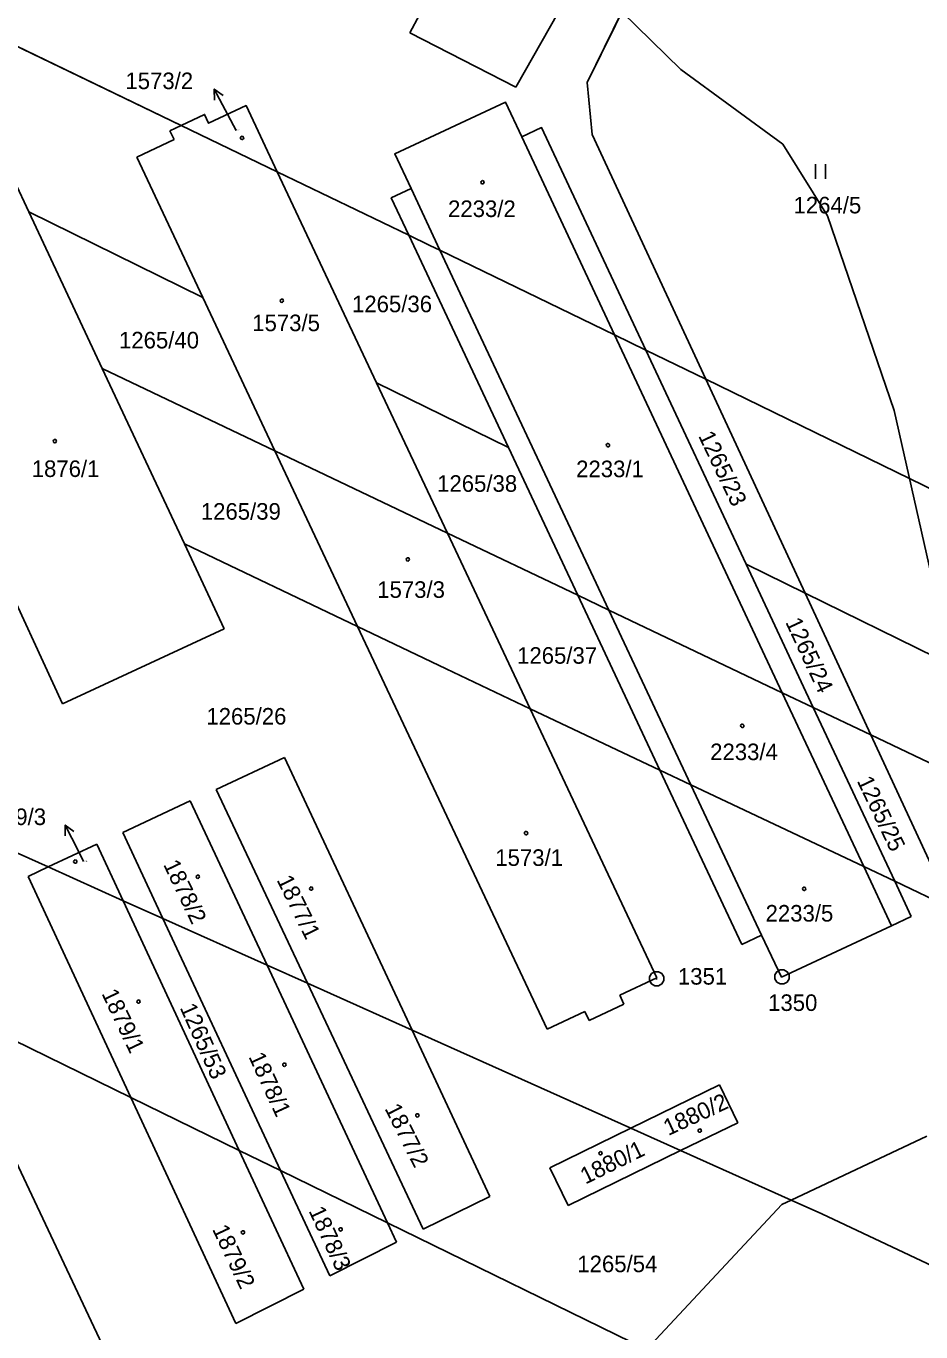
# Model space of a CAD drawing. Extents: x -779618 to -776429, y -1144546 to -1143350.
# Drawn here: x -777167.4 to -777075.6, y -1144114.1 to -1143980.2 of the extents above; entities that cross this region are included whole.
import ezdxf

# ---------------------------------------------------------------- set-up
doc = ezdxf.new("R2010")
doc.units = 0
for name, color, linetype in [('1', 7, 'Continuous'), ('11', 7, 'Continuous'), ('12', 7, 'Continuous'), ('2', 7, 'Continuous'), ('3', 7, 'Continuous'), ('4', 7, 'Continuous'), ('5', 7, 'Continuous'), ('7', 7, 'Continuous'), ('8', 7, 'Continuous')]:
    doc.layers.add(name, color=color, linetype=linetype)

msp = doc.modelspace()

# ---------------------------------------------------------------- linework, layer by layer
at = {"layer": '1'}
for p, q in [((-777093.52, -1143952.82), (-777109.82, -1143985.95)), ((-777128.02, -1143980.84), (-777120.78, -1143967.25)), ((-777109.82, -1143973.51), (-777117.13, -1143986.44)), ((-777182.11, -1143975.59), (-777151.49, -1143990.35)), ((-777117.13, -1143986.44), (-777128.02, -1143980.84)), ((-777109.82, -1143985.95), (-777109.29, -1143991.28)), ((-777148.68, -1143990.13), (-777144.83, -1143988.32)), ((-777144.83, -1143988.32), (-777141.63, -1143995.11)), ((-777129.57, -1143993.28), (-777118.21, -1143987.96)), ((-777118.21, -1143987.96), (-777116.54, -1143991.53)), ((-777151.49, -1143990.35), (-777149.1, -1143989.23)), ((-777149.1, -1143989.23), (-777148.68, -1143990.13)), ((-777152.65, -1143990.9), (-777151.49, -1143990.35)), ((-777152.22, -1143991.8), (-777152.65, -1143990.9)), ((-777151.49, -1143990.35), (-777141.63, -1143995.11)), ((-777116.54, -1143991.53), (-777114.5, -1143990.57)), ((-777114.5, -1143990.57), (-777103.79, -1144013.4)), ((-777109.29, -1143991.28), (-777097.63, -1144016.39)), ((-777156.06, -1143993.61), (-777152.22, -1143991.8)), ((-777149.29, -1144007.99), (-777156.06, -1143993.61)), ((-777127.9, -1143996.84), (-777129.57, -1143993.28)), ((-777141.63, -1143995.11), (-777128.13, -1144001.62)), ((-777141.63, -1143995.11), (-777131.43, -1144016.75)), ((-777167.13, -1143999.23), (-777168.61, -1143996.07)), ((-777129.93, -1143997.79), (-777127.9, -1143996.84)), ((-777128.13, -1144001.62), (-777129.93, -1143997.79)), ((-777167.13, -1143999.23), (-777149.29, -1144007.99)), ((-777167.13, -1143999.23), (-777159.6, -1144015.3)), ((-777128.13, -1144001.62), (-777125.96, -1144002.66)), ((-777128.13, -1144001.62), (-777117.9, -1144023.39)), ((-777125.96, -1144002.66), (-777124.93, -1144003.16)), ((-777124.93, -1144003.16), (-777107.02, -1144011.84)), ((-777149.29, -1144007.99), (-777141.88, -1144023.74)), ((-777107.02, -1144011.84), (-777103.79, -1144013.4)), ((-777103.79, -1144013.4), (-777099.68, -1144015.4)), ((-777103.79, -1144013.4), (-777093.49, -1144035.37)), ((-777159.6, -1144015.3), (-777141.88, -1144023.74)), ((-777159.6, -1144015.3), (-777151.17, -1144033.27)), ((-777099.68, -1144015.4), (-777097.63, -1144016.39)), ((-777131.43, -1144016.75), (-777117.9, -1144023.39)), ((-777131.43, -1144016.75), (-777124.16, -1144032.18)), ((-777097.63, -1144016.39), (-777054.51, -1144037.4)), ((-777097.63, -1144016.39), (-777087.44, -1144038.34)), ((-777163.68, -1144049.68), (-777176.95, -1144020.96)), ((-777141.88, -1144023.74), (-777124.16, -1144032.18)), ((-777141.88, -1144023.74), (-777133.39, -1144041.77)), ((-777117.9, -1144023.39), (-777110.78, -1144038.56)), ((-777124.16, -1144032.18), (-777110.78, -1144038.56)), ((-777124.16, -1144032.18), (-777115.67, -1144050.19)), ((-777133.39, -1144041.77), (-777151.17, -1144033.27)), ((-777151.17, -1144033.27), (-777147.08, -1144042)), ((-777093.49, -1144035.37), (-777087.44, -1144038.34)), ((-777093.49, -1144035.37), (-777086.6, -1144050.07)), ((-777087.44, -1144038.34), (-777074.06, -1144044.91)), ((-777087.44, -1144038.34), (-777080.69, -1144052.88)), ((-777110.78, -1144038.56), (-777107.58, -1144040.08)), ((-777110.78, -1144038.56), (-777102.35, -1144056.49)), ((-777107.58, -1144040.08), (-777089.79, -1144048.55)), ((-777147.08, -1144042), (-777163.68, -1144049.68)), ((-777124.3, -1144046.11), (-777133.39, -1144041.77)), ((-777133.39, -1144041.77), (-777113.94, -1144083.08)), ((-777115.67, -1144050.19), (-777124.3, -1144046.11)), ((-777089.79, -1144048.55), (-777086.6, -1144050.07)), ((-777102.35, -1144056.49), (-777115.67, -1144050.19)), ((-777115.67, -1144050.19), (-777102.66, -1144077.8)), ((-777086.6, -1144050.07), (-777080.69, -1144052.88)), ((-777086.6, -1144050.07), (-777078.24, -1144067.9)), ((-777080.69, -1144052.88), (-777034.39, -1144074.95)), ((-777080.69, -1144052.88), (-777072.46, -1144070.64)), ((-777147.92, -1144058.49), (-777140.89, -1144055.19)), ((-777140.89, -1144055.19), (-777127.79, -1144083.17)), ((-777187.43, -1144056.45), (-777165.16, -1144066.43)), ((-777099.16, -1144058), (-777102.35, -1144056.49)), ((-777093.95, -1144074.37), (-777102.35, -1144056.49)), ((-777147.92, -1144058.49), (-777138.54, -1144078.35)), ((-777081.43, -1144066.39), (-777099.16, -1144058)), ((-777157.5, -1144062.89), (-777150.56, -1144059.63)), ((-777150.56, -1144059.63), (-777142.67, -1144076.5)), ((-777153.38, -1144071.71), (-777157.5, -1144062.89)), ((-777160.14, -1144064.08), (-777165.16, -1144066.43)), ((-777157.44, -1144069.89), (-777160.14, -1144064.08)), ((-777165.16, -1144066.43), (-777167.2, -1144067.39)), ((-777165.16, -1144066.43), (-777157.44, -1144069.89)), ((-777078.24, -1144067.9), (-777081.43, -1144066.39)), ((-777167.2, -1144067.39), (-777156.67, -1144090.07)), ((-777072.46, -1144070.64), (-777078.24, -1144067.9)), ((-777076.55, -1144071.5), (-777078.24, -1144067.9)), ((-777157.44, -1144069.89), (-777153.38, -1144071.71)), ((-777145.53, -1144095.5), (-777157.44, -1144069.89)), ((-777153.38, -1144071.71), (-777142.67, -1144076.5)), ((-777141.3, -1144097.57), (-777153.38, -1144071.71)), ((-777078.58, -1144072.46), (-777076.55, -1144071.5)), ((-777089.88, -1144077.75), (-777078.58, -1144072.46)), ((-777091.92, -1144073.41), (-777093.95, -1144074.37)), ((-777091.92, -1144073.41), (-777089.88, -1144077.75)), ((-777142.67, -1144076.5), (-777138.54, -1144078.35)), ((-777142.67, -1144076.5), (-777130.33, -1144102.93)), ((-777138.54, -1144078.35), (-777127.79, -1144083.17)), ((-777126.64, -1144103.57), (-777138.54, -1144078.35)), ((-777106.48, -1144079.59), (-777102.66, -1144077.8)), ((-777106.48, -1144079.59), (-777106.05, -1144080.5)), ((-777176.03, -1144080.61), (-777156.67, -1144090.07)), ((-777158.22, -1144118.36), (-777176.03, -1144080.61)), ((-777113.94, -1144083.08), (-777110.04, -1144081.26)), ((-777110.04, -1144081.26), (-777109.62, -1144082.17)), ((-777109.62, -1144082.17), (-777106.05, -1144080.5)), ((-777127.79, -1144083.17), (-777105.34, -1144093.23)), ((-777127.79, -1144083.17), (-777119.81, -1144100.22)), ((-777105.34, -1144093.23), (-777096.24, -1144088.79)), ((-777096.24, -1144088.79), (-777094.36, -1144092.67)), ((-777156.67, -1144090.07), (-777145.53, -1144095.5)), ((-777156.67, -1144090.07), (-777145.89, -1144113.28)), ((-777113.65, -1144097.29), (-777105.34, -1144093.23)), ((-777105.34, -1144093.23), (-777100.22, -1144095.52)), ((-777094.36, -1144092.67), (-777100.22, -1144095.52)), ((-777088.89, -1144100.6), (-777074.93, -1144094.03)), ((-777145.53, -1144095.5), (-777141.3, -1144097.57)), ((-777138.92, -1144109.73), (-777145.53, -1144095.5)), ((-777100.22, -1144095.52), (-777111.78, -1144101.16)), ((-777100.22, -1144095.52), (-777088.89, -1144100.6)), ((-777111.78, -1144101.16), (-777113.65, -1144097.29)), ((-777141.3, -1144097.57), (-777130.33, -1144102.93)), ((-777136.25, -1144108.38), (-777141.3, -1144097.57)), ((-777119.81, -1144100.22), (-777126.64, -1144103.57)), ((-777103.71, -1144115.92), (-777089.82, -1144101.04)), ((-777089.82, -1144101.04), (-777088.89, -1144100.6)), ((-777088.89, -1144100.6), (-777085.72, -1144102.02)), ((-776999, -1144142.97), (-777085.72, -1144102.02)), ((-777130.33, -1144102.93), (-777103.71, -1144115.92)), ((-777130.33, -1144102.93), (-777129.39, -1144104.93)), ((-777129.39, -1144104.93), (-777136.25, -1144108.38)), ((-777145.89, -1144113.28), (-777138.92, -1144109.73))]:
    msp.add_line(p, q, dxfattribs=at)
at = {"layer": '11'}
for points in [[(-777233.61, -1143950.34), (-777182.11, -1143975.59), (-777151.49, -1143990.35), (-777149.1, -1143989.23), (-777148.68, -1143990.13), (-777144.83, -1143988.32), (-777141.63, -1143995.11), (-777128.13, -1144001.62), (-777129.93, -1143997.79), (-777127.9, -1143996.84), (-777129.57, -1143993.28), (-777118.21, -1143987.96), (-777116.54, -1143991.53), (-777114.5, -1143990.57), (-777103.79, -1144013.4), (-777099.68, -1144015.4), (-777097.63, -1144016.39), (-777109.29, -1143991.28), (-777109.82, -1143985.95), (-777106.25, -1143978.69)], [(-777106.25, -1143978.69), (-777100.19, -1143984.61), (-777089.74, -1143992.29), (-777085.15, -1143999.64), (-777078.29, -1144019.61), (-777070.38, -1144054.63), (-777064.39, -1144074.9), (-777053.6, -1144104.13), (-777023.35, -1144200.11), (-777006.25, -1144273.89), (-776995.59, -1144305.77), (-776985.2, -1144331.09), (-776979.71, -1144341.4), (-776962.8, -1144366.65), (-776938.27, -1144396.78)]]:
    msp.add_lwpolyline(points, dxfattribs=at)
at = {"layer": '12'}
for p, q in [((-777148.68, -1143990.13), (-777144.83, -1143988.32)), ((-777144.83, -1143988.32), (-777141.63, -1143995.11)), ((-777129.57, -1143993.28), (-777118.21, -1143987.96)), ((-777118.21, -1143987.96), (-777116.54, -1143991.53)), ((-777151.49, -1143990.35), (-777149.1, -1143989.23)), ((-777149.1, -1143989.23), (-777148.68, -1143990.13)), ((-777152.65, -1143990.9), (-777151.49, -1143990.35)), ((-777152.22, -1143991.8), (-777152.65, -1143990.9)), ((-777116.54, -1143991.53), (-777107.02, -1144011.84)), ((-777156.06, -1143993.61), (-777152.22, -1143991.8)), ((-777149.29, -1144007.99), (-777156.06, -1143993.61)), ((-777127.9, -1143996.84), (-777129.57, -1143993.28)), ((-777141.63, -1143995.11), (-777131.43, -1144016.75)), ((-777167.13, -1143999.23), (-777168.61, -1143996.07)), ((-777127.9, -1143996.84), (-777124.93, -1144003.16)), ((-777167.13, -1143999.23), (-777159.6, -1144015.3)), ((-777124.93, -1144003.16), (-777107.58, -1144040.08)), ((-777149.29, -1144007.99), (-777141.88, -1144023.74)), ((-777107.02, -1144011.84), (-777089.79, -1144048.55)), ((-777159.6, -1144015.3), (-777151.17, -1144033.27)), ((-777131.43, -1144016.75), (-777124.16, -1144032.18)), ((-777163.68, -1144049.68), (-777176.95, -1144020.96)), ((-777141.88, -1144023.74), (-777133.39, -1144041.77)), ((-777124.16, -1144032.18), (-777115.67, -1144050.19)), ((-777151.17, -1144033.27), (-777147.08, -1144042)), ((-777107.58, -1144040.08), (-777099.16, -1144058)), ((-777147.08, -1144042), (-777163.68, -1144049.68)), ((-777133.39, -1144041.77), (-777113.94, -1144083.08)), ((-777089.79, -1144048.55), (-777081.43, -1144066.39)), ((-777115.67, -1144050.19), (-777102.66, -1144077.8)), ((-777147.92, -1144058.49), (-777140.89, -1144055.19)), ((-777140.89, -1144055.19), (-777127.79, -1144083.17)), ((-777147.92, -1144058.49), (-777138.54, -1144078.35)), ((-777099.16, -1144058), (-777091.92, -1144073.41)), ((-777157.5, -1144062.89), (-777150.56, -1144059.63)), ((-777150.56, -1144059.63), (-777142.67, -1144076.5)), ((-777153.38, -1144071.71), (-777157.5, -1144062.89)), ((-777160.14, -1144064.08), (-777165.16, -1144066.43)), ((-777157.44, -1144069.89), (-777160.14, -1144064.08)), ((-777165.16, -1144066.43), (-777167.2, -1144067.39)), ((-777081.43, -1144066.39), (-777078.58, -1144072.46)), ((-777167.2, -1144067.39), (-777156.67, -1144090.07)), ((-777145.53, -1144095.5), (-777157.44, -1144069.89)), ((-777141.3, -1144097.57), (-777153.38, -1144071.71)), ((-777089.88, -1144077.75), (-777078.58, -1144072.46)), ((-777091.92, -1144073.41), (-777089.88, -1144077.75)), ((-777142.67, -1144076.5), (-777130.33, -1144102.93)), ((-777126.64, -1144103.57), (-777138.54, -1144078.35)), ((-777106.48, -1144079.59), (-777102.66, -1144077.8)), ((-777106.48, -1144079.59), (-777106.05, -1144080.5)), ((-777158.22, -1144118.36), (-777176.03, -1144080.61)), ((-777113.94, -1144083.08), (-777110.04, -1144081.26)), ((-777110.04, -1144081.26), (-777109.62, -1144082.17)), ((-777109.62, -1144082.17), (-777106.05, -1144080.5)), ((-777127.79, -1144083.17), (-777119.81, -1144100.22)), ((-777105.34, -1144093.23), (-777096.24, -1144088.79)), ((-777096.24, -1144088.79), (-777094.36, -1144092.67)), ((-777156.67, -1144090.07), (-777145.89, -1144113.28)), ((-777113.65, -1144097.29), (-777105.34, -1144093.23)), ((-777094.36, -1144092.67), (-777100.22, -1144095.52)), ((-777138.92, -1144109.73), (-777145.53, -1144095.5)), ((-777100.22, -1144095.52), (-777111.78, -1144101.16)), ((-777111.78, -1144101.16), (-777113.65, -1144097.29)), ((-777136.25, -1144108.38), (-777141.3, -1144097.57)), ((-777119.81, -1144100.22), (-777126.64, -1144103.57)), ((-777130.33, -1144102.93), (-777129.39, -1144104.93)), ((-777129.39, -1144104.93), (-777136.25, -1144108.38)), ((-777145.89, -1144113.28), (-777138.92, -1144109.73))]:
    msp.add_line(p, q, dxfattribs=at)
at = {"layer": '3'}
for p, q in [((-777086.36, -1143994.34), (-777086.36, -1143995.84)), ((-777085.36, -1143995.84), (-777085.36, -1143994.34))]:
    msp.add_line(p, q, dxfattribs=at)
at = {"layer": '4'}
for p, q in [((-777116.54, -1143991.53), (-777107.02, -1144011.84)), ((-777127.9, -1143996.84), (-777124.93, -1144003.16)), ((-777124.93, -1144003.16), (-777107.58, -1144040.08)), ((-777107.02, -1144011.84), (-777089.79, -1144048.55)), ((-777107.58, -1144040.08), (-777099.16, -1144058)), ((-777089.79, -1144048.55), (-777081.43, -1144066.39)), ((-777099.16, -1144058), (-777091.92, -1144073.41)), ((-777081.43, -1144066.39), (-777078.58, -1144072.46))]:
    msp.add_line(p, q, dxfattribs=at)
at = {"layer": '5'}
for points in [[(-777145.25, -1143991.47), (-777145.15, -1143991.49), (-777145.1, -1143991.58), (-777145.08, -1143991.64), (-777145.1, -1143991.73), (-777145.18, -1143991.8), (-777145.25, -1143991.81), (-777145.34, -1143991.78), (-777145.4, -1143991.72), (-777145.42, -1143991.64), (-777145.4, -1143991.55), (-777145.32, -1143991.48)], [(-777120.56, -1143996.02), (-777120.46, -1143996.04), (-777120.41, -1143996.13), (-777120.39, -1143996.19), (-777120.41, -1143996.28), (-777120.49, -1143996.35), (-777120.56, -1143996.36), (-777120.65, -1143996.33), (-777120.71, -1143996.27), (-777120.73, -1143996.19), (-777120.71, -1143996.1), (-777120.63, -1143996.03)], [(-777141.16, -1144008.17), (-777141.06, -1144008.19), (-777141.01, -1144008.28), (-777140.99, -1144008.34), (-777141.01, -1144008.43), (-777141.09, -1144008.5), (-777141.16, -1144008.51), (-777141.25, -1144008.48), (-777141.31, -1144008.42), (-777141.33, -1144008.34), (-777141.31, -1144008.25), (-777141.23, -1144008.18)], [(-777164.47, -1144022.57), (-777164.37, -1144022.59), (-777164.32, -1144022.68), (-777164.3, -1144022.74), (-777164.32, -1144022.83), (-777164.4, -1144022.9), (-777164.47, -1144022.91), (-777164.56, -1144022.88), (-777164.62, -1144022.82), (-777164.64, -1144022.74), (-777164.62, -1144022.65), (-777164.54, -1144022.58)], [(-777107.68, -1144022.99), (-777107.58, -1144023.01), (-777107.53, -1144023.1), (-777107.51, -1144023.16), (-777107.53, -1144023.25), (-777107.61, -1144023.32), (-777107.68, -1144023.33), (-777107.77, -1144023.3), (-777107.83, -1144023.24), (-777107.85, -1144023.16), (-777107.83, -1144023.07), (-777107.75, -1144023)], [(-777128.23, -1144034.7), (-777128.13, -1144034.72), (-777128.08, -1144034.81), (-777128.06, -1144034.87), (-777128.08, -1144034.96), (-777128.16, -1144035.03), (-777128.23, -1144035.04), (-777128.32, -1144035.01), (-777128.38, -1144034.95), (-777128.4, -1144034.87), (-777128.38, -1144034.78), (-777128.3, -1144034.71)], [(-777093.89, -1144051.78), (-777093.79, -1144051.8), (-777093.74, -1144051.89), (-777093.72, -1144051.95), (-777093.74, -1144052.04), (-777093.82, -1144052.11), (-777093.89, -1144052.12), (-777093.98, -1144052.09), (-777094.04, -1144052.03), (-777094.06, -1144051.95), (-777094.04, -1144051.86), (-777093.96, -1144051.79)], [(-777116.09, -1144062.79), (-777115.99, -1144062.81), (-777115.94, -1144062.9), (-777115.92, -1144062.96), (-777115.94, -1144063.05), (-777116.02, -1144063.12), (-777116.09, -1144063.13), (-777116.18, -1144063.1), (-777116.24, -1144063.04), (-777116.26, -1144062.96), (-777116.24, -1144062.87), (-777116.16, -1144062.8)], [(-777162.37, -1144065.71), (-777162.27, -1144065.73), (-777162.22, -1144065.82), (-777162.2, -1144065.88), (-777162.22, -1144065.97), (-777162.3, -1144066.04), (-777162.37, -1144066.05), (-777162.46, -1144066.02), (-777162.52, -1144065.96), (-777162.54, -1144065.88), (-777162.52, -1144065.79), (-777162.44, -1144065.72)], [(-777149.79, -1144067.26), (-777149.69, -1144067.28), (-777149.64, -1144067.37), (-777149.62, -1144067.43), (-777149.64, -1144067.52), (-777149.72, -1144067.59), (-777149.79, -1144067.6), (-777149.88, -1144067.57), (-777149.94, -1144067.51), (-777149.96, -1144067.43), (-777149.94, -1144067.34), (-777149.86, -1144067.27)], [(-777138.15, -1144068.48), (-777138.05, -1144068.5), (-777138, -1144068.59), (-777137.98, -1144068.65), (-777138, -1144068.74), (-777138.08, -1144068.81), (-777138.15, -1144068.82), (-777138.24, -1144068.79), (-777138.3, -1144068.73), (-777138.32, -1144068.65), (-777138.3, -1144068.56), (-777138.22, -1144068.49)], [(-777087.54, -1144068.5), (-777087.44, -1144068.52), (-777087.39, -1144068.61), (-777087.37, -1144068.67), (-777087.39, -1144068.76), (-777087.47, -1144068.83), (-777087.54, -1144068.84), (-777087.63, -1144068.81), (-777087.69, -1144068.75), (-777087.71, -1144068.67), (-777087.69, -1144068.58), (-777087.61, -1144068.51)], [(-777155.88, -1144080.07), (-777155.78, -1144080.09), (-777155.73, -1144080.18), (-777155.71, -1144080.24), (-777155.73, -1144080.33), (-777155.81, -1144080.4), (-777155.88, -1144080.41), (-777155.97, -1144080.38), (-777156.03, -1144080.32), (-777156.05, -1144080.24), (-777156.03, -1144080.15), (-777155.95, -1144080.08)], [(-777140.9, -1144086.55), (-777140.8, -1144086.57), (-777140.75, -1144086.66), (-777140.73, -1144086.72), (-777140.75, -1144086.81), (-777140.83, -1144086.88), (-777140.9, -1144086.89), (-777140.99, -1144086.86), (-777141.05, -1144086.8), (-777141.07, -1144086.72), (-777141.05, -1144086.63), (-777140.97, -1144086.56)], [(-777127.25, -1144091.74), (-777127.15, -1144091.76), (-777127.1, -1144091.85), (-777127.08, -1144091.91), (-777127.1, -1144092), (-777127.18, -1144092.07), (-777127.25, -1144092.08), (-777127.34, -1144092.05), (-777127.4, -1144091.99), (-777127.42, -1144091.91), (-777127.4, -1144091.82), (-777127.32, -1144091.75)], [(-777098.26, -1144093.31), (-777098.16, -1144093.33), (-777098.11, -1144093.42), (-777098.09, -1144093.48), (-777098.11, -1144093.57), (-777098.19, -1144093.64), (-777098.26, -1144093.65), (-777098.35, -1144093.62), (-777098.41, -1144093.56), (-777098.43, -1144093.48), (-777098.41, -1144093.39), (-777098.33, -1144093.32)], [(-777108.45, -1144095.63), (-777108.35, -1144095.65), (-777108.3, -1144095.74), (-777108.28, -1144095.8), (-777108.3, -1144095.89), (-777108.38, -1144095.96), (-777108.45, -1144095.97), (-777108.54, -1144095.94), (-777108.6, -1144095.88), (-777108.62, -1144095.8), (-777108.6, -1144095.71), (-777108.52, -1144095.64)], [(-777145.16, -1144103.75), (-777145.06, -1144103.77), (-777145.01, -1144103.86), (-777144.99, -1144103.92), (-777145.01, -1144104.01), (-777145.09, -1144104.08), (-777145.16, -1144104.09), (-777145.25, -1144104.06), (-777145.31, -1144104), (-777145.33, -1144103.92), (-777145.31, -1144103.83), (-777145.23, -1144103.76)], [(-777135.13, -1144103.44), (-777135.03, -1144103.46), (-777134.98, -1144103.55), (-777134.96, -1144103.61), (-777134.98, -1144103.7), (-777135.06, -1144103.77), (-777135.13, -1144103.78), (-777135.22, -1144103.75), (-777135.28, -1144103.69), (-777135.3, -1144103.61), (-777135.28, -1144103.52), (-777135.2, -1144103.45)]]:
    msp.add_lwpolyline(points, close=True, dxfattribs=at)
at = {"layer": '7'}
for p, q in [((-777148.1, -1143986.63), (-777146.69, -1143989.28)), ((-777145.84, -1143990.86), (-777146.69, -1143989.28)), ((-777163.39, -1144062.13), (-777162.05, -1144064.81)), ((-777161.52, -1144065.88), (-777162.05, -1144064.81))]:
    msp.add_line(p, q, dxfattribs=at)
for points in [[(-777148.07, -1143987.75), (-777148.1, -1143986.63), (-777147.19, -1143987.28)], [(-777163.39, -1144063.24), (-777163.39, -1144062.13), (-777162.5, -1144062.8)]]:
    msp.add_lwpolyline(points, dxfattribs=at)
at = {"layer": '8'}
for p, q in [((-777102.73, -1144077.89), (-777102.63, -1144077.89)), ((-777089.86, -1144077.7), (-777089.76, -1144077.7))]:
    msp.add_line(p, q, dxfattribs=at)
for points in [[(-777102.49, -1144077.17), (-777102.15, -1144077.36), (-777101.96, -1144077.7), (-777101.96, -1144078.09), (-777102.15, -1144078.43), (-777102.49, -1144078.62), (-777102.88, -1144078.62), (-777103.22, -1144078.43), (-777103.41, -1144078.09), (-777103.41, -1144077.7), (-777103.22, -1144077.36), (-777102.88, -1144077.17)], [(-777089.62, -1144076.98), (-777089.28, -1144077.17), (-777089.09, -1144077.51), (-777089.09, -1144077.9), (-777089.28, -1144078.24), (-777089.62, -1144078.43), (-777090.01, -1144078.43), (-777090.35, -1144078.24), (-777090.54, -1144077.9), (-777090.54, -1144077.51), (-777090.35, -1144077.17), (-777090.01, -1144076.98)]]:
    msp.add_lwpolyline(points, close=True, dxfattribs=at)

# ---------------------------------------------------------------- texts
at = {"layer": '2'}
for s, height, p in [('1573/2', 0.1, (-777145.82, -1143990.86)), ('2233/2', 1.7, (-777124.1, -1143999.75)), ('1264/5', 1.7, (-777088.63, -1143999.38)), ('1265/36', 1.7, (-777133.96, -1144009.52)), ('1573/5', 1.7, (-777144.2, -1144011.46)), ('1265/40', 1.7, (-777157.88, -1144013.23)), ('1876/1', 1.7, (-777166.84, -1144026.42)), ('2233/1', 1.7, (-777110.95, -1144026.44)), ('1265/38', 1.7, (-777125.22, -1144027.94)), ('1265/39', 1.7, (-777149.48, -1144030.8)), ('1573/3', 1.7, (-777131.37, -1144038.82)), ('1265/37', 1.7, (-777117.01, -1144045.58)), ('1265/26', 1.7, (-777148.91, -1144051.82)), ('2233/4', 1.7, (-777097.19, -1144055.47)), ('1573/1', 1.7, (-777119.25, -1144066.32)), ('1879/3', 0.1, (-777161.5, -1144065.88)), ('2233/5', 1.7, (-777091.5, -1144072.03)), ('1265/54', 1.7, (-777110.83, -1144108))]:
    msp.add_text(s, height=height, dxfattribs=at).set_placement(p)
for s, rotation, p in [('1265/23', 295.7035, (-777098.45, -1144022.19)), ('1265/24', 295.016, (-777089.5, -1144041.31)), ('1265/25', 295.5316, (-777082.16, -1144057.59)), ('1878/2', 295.6462, (-777153.37, -1144066.17)), ('1877/1', 296.0473, (-777141.72, -1144067.76)), ('1879/1', 295.417, (-777159.7, -1144079.41)), ('1265/53', 294.0419, (-777151.66, -1144080.86)), ('1878/1', 294.6722, (-777144.61, -1144085.89)), ('1880/2', 24.8664, (-777101.49, -1144094.04)), ('1877/2', 296.7348, (-777130.64, -1144091.21)), ('1880/1', 26.2415, (-777109.99, -1144099.02)), ('1878/3', 294.7868, (-777138.44, -1144101.7)), ('1879/2', 295.2452, (-777148.34, -1144103.59))]:
    msp.add_text(s, height=1.7, rotation=rotation, dxfattribs=at).set_placement(p)
at = {"layer": '7'}
for s, p in [('1573/2', (-777157.22, -1143986.63)), ('1879/3', (-777172.32, -1144062.13))]:
    msp.add_text(s, height=1.7, dxfattribs=at).set_placement(p)
at = {"layer": '8'}
for s, p in [('1351', (-777100.5, -1144078.5)), ('1350', (-777091.24, -1144081.2))]:
    msp.add_text(s, height=1.7, dxfattribs=at).set_placement(p)

doc.saveas('drawing.dxf')
